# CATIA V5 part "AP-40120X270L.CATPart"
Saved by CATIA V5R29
Part number: AP-40120X270L
Bounding box of the stored display mesh (mm): x -135 to 135, y -60 to 60, z -20 to 20
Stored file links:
  C:\Users\Administrator\Desktop\프로젝트\Boxfold\AP-40120X270L.CATPart
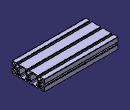
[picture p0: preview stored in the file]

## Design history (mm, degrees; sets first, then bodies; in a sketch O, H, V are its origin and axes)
Body1 (main body)
  Sketch1 on yz-plane, origin (0, 0, 0), H (0, 1, 0), V (0, 0, 1)
    point P1 (-60, -19)
    circle A1 centre (53.5, -13.5) radius 4
    circle A2 centre (53.5, 13.5) radius 4
    circle A3 centre (-53.5, -13.5) radius 4
    circle A4 centre (-53.5, 13.5) radius 4
    arc A5 centre (-38.0088, -3.1185) radius 0.3 from (-37.7966, -2.9064) to (-38.1702, -2.8656) ccw
    line L1 (-37.7966, -2.9064) -> (-37.1018, -3.6012)
    arc A6 centre (-36.8897, -3.3891) radius 0.3 from (-37.1018, -3.6012) to (-36.6868, -3.6101) ccw
    arc A7 centre (-40, 0) radius 4.9 from (-36.6868, -3.6101) to (-36.3857, -3.3086) ccw
    arc A8 centre (-36.607, -3.106) radius 0.3 from (-36.3857, -3.3086) to (-36.3949, -2.8939) ccw
    line L2 (-36.3949, -2.8939) -> (-37.0904, -2.1983)
    arc A9 centre (-36.8783, -1.9862) radius 0.3 from (-37.1314, -1.8252) to (-37.0904, -2.1983) ccw
    arc A10 centre (-40, 0) radius 3.4 from (-37.1314, -1.8252) to (-37.1323, 1.8265) ccw
    arc A11 centre (-36.8792, 1.9877) radius 0.3 from (-37.0914, 2.1998) to (-37.1323, 1.8265) ccw
    line L3 (-37.0914, 2.1998) -> (-36.396, 2.8952)
    arc A12 centre (-36.6081, 3.1073) radius 0.3 from (-36.396, 2.8952) to (-36.3869, 3.31) ccw
    arc A13 centre (-40, 0) radius 4.9 from (-36.3869, 3.31) to (-36.6881, 3.6113) ccw
    arc A14 centre (-36.8909, 3.3902) radius 0.3 from (-36.6881, 3.6113) to (-37.103, 3.6024) ccw
    line L4 (-37.103, 3.6024) -> (-37.7981, 2.9073)
    arc A15 centre (-38.0102, 3.1194) radius 0.3 from (-38.1716, 2.8665) to (-37.7981, 2.9073) ccw
    arc A16 centre (-40, 0) radius 3.4 from (-38.1716, 2.8665) to (-41.8252, 2.8686) ccw
    arc A17 centre (-41.9862, 3.1217) radius 0.3 from (-42.1983, 2.9096) to (-41.8252, 2.8686) ccw
    line L5 (-42.1983, 2.9096) -> (-42.8939, 3.6051)
    arc A18 centre (-43.106, 3.393) radius 0.3 from (-42.8939, 3.6051) to (-43.3086, 3.6143) ccw
    arc A19 centre (-40, 0) radius 4.9 from (-43.3086, 3.6143) to (-43.6101, 3.3132) ccw
    arc A20 centre (-43.3891, 3.1103) radius 0.3 from (-43.6101, 3.3132) to (-43.6012, 2.8982) ccw
    line L6 (-43.6012, 2.8982) -> (-42.9064, 2.2034)
    arc A21 centre (-43.1185, 1.9912) radius 0.3 from (-42.8656, 1.8298) to (-42.9064, 2.2034) ccw
    arc A22 centre (-40, 0) radius 3.4 from (-42.8656, 1.8298) to (-42.8665, -1.8284) ccw
    arc A23 centre (-43.1194, -1.9898) radius 0.3 from (-42.9073, -2.2019) to (-42.8665, -1.8284) ccw
    line L7 (-42.9073, -2.2019) -> (-43.6024, -2.897)
    arc A24 centre (-43.3902, -3.1091) radius 0.3 from (-43.6024, -2.897) to (-43.6113, -3.3119) ccw
    arc A25 centre (-40, 0) radius 4.9 from (-43.6113, -3.3119) to (-43.31, -3.6131) ccw
    arc A26 centre (-43.1073, -3.3919) radius 0.3 from (-43.31, -3.6131) to (-42.8952, -3.604) ccw
    line L8 (-42.8952, -3.604) -> (-42.1998, -2.9086)
    arc A27 centre (-41.9877, -3.1208) radius 0.3 from (-41.8265, -2.8677) to (-42.1998, -2.9086) ccw
    arc A28 centre (-40, 0) radius 3.4 from (-41.8265, -2.8677) to (-38.1702, -2.8656) ccw
    line L9 (39.6951, 6.0049) -> (40, 5.7)
    line L10 (40, 5.7) -> (40.3049, 6.0049)
    arc A29 centre (40, 15.5) radius 9.5 from (40.3049, 6.0049) to (47.0734, 9.1583) ccw
    arc A30 centre (46.85, 9.3585) radius 0.3 from (47.0734, 9.1583) to (47.15, 9.3585) ccw
    line L11 (47.15, 9.3585) -> (47.15, 15.7)
    arc A31 centre (46.85, 15.7) radius 0.3 from (47.15, 15.7) to (46.85, 16) ccw
    line L12 (46.85, 16) -> (44.65, 16)
    arc A32 centre (44.65, 16.5) radius 0.5 from (44.15, 16.5) to (44.65, 16) ccw
    line L13 (44.15, 16.5) -> (44.15, 19.5)
    arc A33 centre (44.65, 19.5) radius 0.5 from (44.65, 20) to (44.15, 19.5) ccw
    line L14 (44.65, 20) -> (59, 20)
    arc A34 centre (59, 19) radius 1 from (60, 19) to (59, 20) ccw
    line L15 (60, 19) -> (60, 4.65)
    arc A35 centre (59.5, 4.65) radius 0.5 from (59.5, 4.15) to (60, 4.65) ccw
    line L16 (59.5, 4.15) -> (56.5, 4.15)
    arc A36 centre (56.5, 4.65) radius 0.5 from (56, 4.65) to (56.5, 4.15) ccw
    line L17 (56, 4.65) -> (56, 6.85)
    arc A37 centre (55.7, 6.85) radius 0.3 from (56, 6.85) to (55.7, 7.15) ccw
    line L18 (55.7, 7.15) -> (49.3585, 7.15)
    arc A38 centre (49.3585, 6.85) radius 0.3 from (49.3585, 7.15) to (49.1583, 7.0734) ccw
    arc A39 centre (55.5, 0) radius 9.5 from (49.1583, 7.0734) to (46.0049, 0.3049) ccw
    line L19 (46.0049, 0.3049) -> (45.7, 0)
    line L20 (45.7, 0) -> (46.0049, -0.3049)
    arc A40 centre (55.5, 0) radius 9.5 from (46.0049, -0.3049) to (49.1583, -7.0734) ccw
    arc A41 centre (49.3585, -6.85) radius 0.3 from (49.1583, -7.0734) to (49.3585, -7.15) ccw
    line L21 (49.3585, -7.15) -> (55.7, -7.15)
    arc A42 centre (55.7, -6.85) radius 0.3 from (55.7, -7.15) to (56, -6.85) ccw
    line L22 (56, -6.85) -> (56, -4.65)
    arc A43 centre (56.5, -4.65) radius 0.5 from (56.5, -4.15) to (56, -4.65) ccw
    line L23 (56.5, -4.15) -> (59.5, -4.15)
    arc A44 centre (59.5, -4.65) radius 0.5 from (60, -4.65) to (59.5, -4.15) ccw
    line L24 (60, -4.65) -> (60, -19)
    arc A45 centre (59, -19) radius 1 from (59, -20) to (60, -19) ccw
    line L25 (59, -20) -> (44.65, -20)
    arc A46 centre (44.65, -19.5) radius 0.5 from (44.15, -19.5) to (44.65, -20) ccw
    line L26 (44.15, -19.5) -> (44.15, -16.5)
    arc A47 centre (44.65, -16.5) radius 0.5 from (44.65, -16) to (44.15, -16.5) ccw
    line L27 (44.65, -16) -> (46.85, -16)
    arc A48 centre (46.85, -15.7) radius 0.3 from (46.85, -16) to (47.15, -15.7) ccw
    line L28 (47.15, -15.7) -> (47.15, -9.3585)
    arc A49 centre (46.85, -9.3585) radius 0.3 from (47.15, -9.3585) to (47.0734, -9.1583) ccw
    arc A50 centre (40, -15.5) radius 9.5 from (47.0734, -9.1583) to (40.3049, -6.0049) ccw
    line L29 (40.3049, -6.0049) -> (40, -5.7)
    line L30 (40, -5.7) -> (39.6951, -6.0049)
    arc A51 centre (40, -15.5) radius 9.5 from (39.6951, -6.0049) to (32.9266, -9.1583) ccw
    arc A52 centre (33.15, -9.3585) radius 0.3 from (32.9266, -9.1583) to (32.85, -9.3585) ccw
    line L31 (32.85, -9.3585) -> (32.85, -15.7)
    arc A53 centre (33.15, -15.7) radius 0.3 from (32.85, -15.7) to (33.15, -16) ccw
    line L32 (33.15, -16) -> (35.35, -16)
    arc A54 centre (35.35, -16.5) radius 0.5 from (35.85, -16.5) to (35.35, -16) ccw
    line L33 (35.85, -16.5) -> (35.85, -19.5)
    arc A55 centre (35.35, -19.5) radius 0.5 from (35.35, -20) to (35.85, -19.5) ccw
    line L34 (35.35, -20) -> (4.65, -20)
    arc A56 centre (4.65, -19.5) radius 0.5 from (4.15, -19.5) to (4.65, -20) ccw
    line L35 (4.15, -19.5) -> (4.15, -16.5)
    arc A57 centre (4.65, -16.5) radius 0.5 from (4.65, -16) to (4.15, -16.5) ccw
    line L36 (4.65, -16) -> (6.85, -16)
    arc A58 centre (6.85, -15.7) radius 0.3 from (6.85, -16) to (7.15, -15.7) ccw
    line L37 (7.15, -15.7) -> (7.15, -9.3585)
    arc A59 centre (6.85, -9.3585) radius 0.3 from (7.15, -9.3585) to (7.0734, -9.1583) ccw
    arc A60 centre (0, -15.5) radius 9.5 from (7.0734, -9.1583) to (0.3049, -6.0049) ccw
    line L38 (0.3049, -6.0049) -> (0, -5.7)
    line L39 (0, -5.7) -> (-0.3049, -6.0049)
    arc A61 centre (0, -15.5) radius 9.5 from (-0.3049, -6.0049) to (-7.0734, -9.1583) ccw
    arc A62 centre (-6.85, -9.3585) radius 0.3 from (-7.0734, -9.1583) to (-7.15, -9.3585) ccw
    line L40 (-7.15, -9.3585) -> (-7.15, -15.7)
    arc A63 centre (-6.85, -15.7) radius 0.3 from (-7.15, -15.7) to (-6.85, -16) ccw
    line L41 (-6.85, -16) -> (-4.65, -16)
    arc A64 centre (-4.65, -16.5) radius 0.5 from (-4.15, -16.5) to (-4.65, -16) ccw
    line L42 (-4.15, -16.5) -> (-4.15, -19.5)
    arc A65 centre (-4.65, -19.5) radius 0.5 from (-4.65, -20) to (-4.15, -19.5) ccw
    line L43 (-4.65, -20) -> (-35.35, -20)
    arc A66 centre (-35.35, -19.5) radius 0.5 from (-35.85, -19.5) to (-35.35, -20) ccw
    line L44 (-35.85, -19.5) -> (-35.85, -16.5)
    arc A67 centre (-35.35, -16.5) radius 0.5 from (-35.35, -16) to (-35.85, -16.5) ccw
    line L45 (-35.35, -16) -> (-33.15, -16)
    arc A68 centre (-33.15, -15.7) radius 0.3 from (-33.15, -16) to (-32.85, -15.7) ccw
    line L46 (-32.85, -15.7) -> (-32.85, -9.3585)
    arc A69 centre (-33.15, -9.3585) radius 0.3 from (-32.85, -9.3585) to (-32.9266, -9.1583) ccw
    arc A70 centre (-40, -15.5) radius 9.5 from (-32.9266, -9.1583) to (-39.6951, -6.0049) ccw
    line L47 (-39.6951, -6.0049) -> (-40, -5.7)
    line L48 (-40, -5.7) -> (-40.3049, -6.0049)
    arc A71 centre (-40, -15.5) radius 9.5 from (-40.3049, -6.0049) to (-47.0734, -9.1583) ccw
    arc A72 centre (-46.85, -9.3585) radius 0.3 from (-47.0734, -9.1583) to (-47.15, -9.3585) ccw
    line L49 (-47.15, -9.3585) -> (-47.15, -15.7)
    arc A73 centre (-46.85, -15.7) radius 0.3 from (-47.15, -15.7) to (-46.85, -16) ccw
    line L50 (-46.85, -16) -> (-44.65, -16)
    arc A74 centre (-44.65, -16.5) radius 0.5 from (-44.15, -16.5) to (-44.65, -16) ccw
    line L51 (-44.15, -16.5) -> (-44.15, -19.5)
    arc A75 centre (-44.65, -19.5) radius 0.5 from (-44.65, -20) to (-44.15, -19.5) ccw
    line L52 (-44.65, -20) -> (-58, -20)
    line L53 (-58, -20) -> (-59, -20)
    arc A76 centre (-59, -19) radius 1 from (-60, -19) to (-59, -20) ccw
    line L54 (-60, -19) -> (-60, -4.65)
    arc A77 centre (-59.5, -4.65) radius 0.5 from (-59.5, -4.15) to (-60, -4.65) ccw
    line L55 (-59.5, -4.15) -> (-56.5, -4.15)
    arc A78 centre (-56.5, -4.65) radius 0.5 from (-56, -4.65) to (-56.5, -4.15) ccw
    line L56 (-56, -4.65) -> (-56, -6.85)
    arc A79 centre (-55.7, -6.85) radius 0.3 from (-56, -6.85) to (-55.7, -7.15) ccw
    line L57 (-55.7, -7.15) -> (-49.3585, -7.15)
    arc A80 centre (-49.3585, -6.85) radius 0.3 from (-49.3585, -7.15) to (-49.1583, -7.0734) ccw
    arc A81 centre (-55.5, 0) radius 9.5 from (-49.1583, -7.0734) to (-46.0049, -0.3049) ccw
    line L58 (-46.0049, -0.3049) -> (-45.7, 0)
    line L59 (-45.7, 0) -> (-46.0049, 0.3049)
    arc A82 centre (-55.5, 0) radius 9.5 from (-46.0049, 0.3049) to (-49.1583, 7.0734) ccw
    arc A83 centre (-49.3585, 6.85) radius 0.3 from (-49.1583, 7.0734) to (-49.3585, 7.15) ccw
    line L60 (-49.3585, 7.15) -> (-55.7, 7.15)
    arc A84 centre (-55.7, 6.85) radius 0.3 from (-55.7, 7.15) to (-56, 6.85) ccw
    line L61 (-56, 6.85) -> (-56, 4.65)
    arc A85 centre (-56.5, 4.65) radius 0.5 from (-56.5, 4.15) to (-56, 4.65) ccw
    line L62 (-56.5, 4.15) -> (-59.5, 4.15)
    arc A86 centre (-59.5, 4.65) radius 0.5 from (-60, 4.65) to (-59.5, 4.15) ccw
    line L63 (-60, 4.65) -> (-60, 19)
    arc A87 centre (-59, 19) radius 1 from (-59, 20) to (-60, 19) ccw
    line L64 (-59, 20) -> (-58, 20)
    line L65 (-58, 20) -> (-44.65, 20)
    arc A88 centre (-44.65, 19.5) radius 0.5 from (-44.15, 19.5) to (-44.65, 20) ccw
    line L66 (-44.15, 19.5) -> (-44.15, 16.5)
    arc A89 centre (-44.65, 16.5) radius 0.5 from (-44.65, 16) to (-44.15, 16.5) ccw
    line L67 (-44.65, 16) -> (-46.85, 16)
    arc A90 centre (-46.85, 15.7) radius 0.3 from (-46.85, 16) to (-47.15, 15.7) ccw
    line L68 (-47.15, 15.7) -> (-47.15, 9.3585)
    arc A91 centre (-46.85, 9.3585) radius 0.3 from (-47.15, 9.3585) to (-47.0734, 9.1583) ccw
    arc A92 centre (-40, 15.5) radius 9.5 from (-47.0734, 9.1583) to (-40.3049, 6.0049) ccw
    line L69 (-40.3049, 6.0049) -> (-40, 5.7)
    line L70 (-40, 5.7) -> (-39.6951, 6.0049)
    arc A93 centre (-40, 15.5) radius 9.5 from (-39.6951, 6.0049) to (-32.9266, 9.1583) ccw
    arc A94 centre (-33.15, 9.3585) radius 0.3 from (-32.9266, 9.1583) to (-32.85, 9.3585) ccw
    line L71 (-32.85, 9.3585) -> (-32.85, 15.7)
    arc A95 centre (-33.15, 15.7) radius 0.3 from (-32.85, 15.7) to (-33.15, 16) ccw
    line L72 (-33.15, 16) -> (-35.35, 16)
    arc A96 centre (-35.35, 16.5) radius 0.5 from (-35.85, 16.5) to (-35.35, 16) ccw
    line L73 (-35.85, 16.5) -> (-35.85, 19.5)
    arc A97 centre (-35.35, 19.5) radius 0.5 from (-35.35, 20) to (-35.85, 19.5) ccw
    line L74 (-35.35, 20) -> (-4.65, 20)
    arc A98 centre (-4.65, 19.5) radius 0.5 from (-4.15, 19.5) to (-4.65, 20) ccw
    line L75 (-4.15, 19.5) -> (-4.15, 16.5)
    arc A99 centre (-4.65, 16.5) radius 0.5 from (-4.65, 16) to (-4.15, 16.5) ccw
    line L76 (-4.65, 16) -> (-6.85, 16)
    arc A100 centre (-6.85, 15.7) radius 0.3 from (-6.85, 16) to (-7.15, 15.7) ccw
    line L77 (-7.15, 15.7) -> (-7.15, 9.3585)
    arc A101 centre (-6.85, 9.3585) radius 0.3 from (-7.15, 9.3585) to (-7.0734, 9.1583) ccw
    arc A102 centre (0, 15.5) radius 9.5 from (-7.0734, 9.1583) to (-0.3049, 6.0049) ccw
    line L78 (-0.3049, 6.0049) -> (0, 5.7)
    line L79 (0, 5.7) -> (0.3049, 6.0049)
    arc A103 centre (0, 15.5) radius 9.5 from (0.3049, 6.0049) to (7.0734, 9.1583) ccw
    arc A104 centre (6.85, 9.3585) radius 0.3 from (7.0734, 9.1583) to (7.15, 9.3585) ccw
    line L80 (7.15, 9.3585) -> (7.15, 15.7)
    arc A105 centre (6.85, 15.7) radius 0.3 from (7.15, 15.7) to (6.85, 16) ccw
    line L81 (6.85, 16) -> (4.65, 16)
    arc A106 centre (4.65, 16.5) radius 0.5 from (4.15, 16.5) to (4.65, 16) ccw
    line L82 (4.15, 16.5) -> (4.15, 19.5)
    arc A107 centre (4.65, 19.5) radius 0.5 from (4.65, 20) to (4.15, 19.5) ccw
    line L83 (4.65, 20) -> (35.35, 20)
    arc A108 centre (35.35, 19.5) radius 0.5 from (35.85, 19.5) to (35.35, 20) ccw
    line L84 (35.85, 19.5) -> (35.85, 16.5)
    arc A109 centre (35.35, 16.5) radius 0.5 from (35.35, 16) to (35.85, 16.5) ccw
    line L85 (35.35, 16) -> (33.15, 16)
    arc A110 centre (33.15, 15.7) radius 0.3 from (33.15, 16) to (32.85, 15.7) ccw
    line L86 (32.85, 15.7) -> (32.85, 9.3585)
    arc A111 centre (33.15, 9.3585) radius 0.3 from (32.85, 9.3585) to (32.9266, 9.1583) ccw
    arc A112 centre (40, 15.5) radius 9.5 from (32.9266, 9.1583) to (39.6951, 6.0049) ccw
    arc A113 centre (13.15, -14) radius 3 from (10.15, -14) to (13.15, -17) ccw
    line L87 (13.15, -17) -> (26.85, -17)
    arc A114 centre (26.85, -14) radius 3 from (26.85, -17) to (29.85, -14) ccw
    line L88 (29.85, -14) -> (29.85, -8.9422)
    arc A115 centre (20, -0.0053) radius 13.3 from (29.85, -8.9422) to (29.85, 8.9315) ccw
    line L89 (29.85, 8.9315) -> (29.85, 14)
    arc A116 centre (26.85, 14) radius 3 from (29.85, 14) to (26.85, 17) ccw
    line L90 (26.85, 17) -> (13.15, 17)
    arc A117 centre (13.15, 14) radius 3 from (13.15, 17) to (10.15, 14) ccw
    line L91 (10.15, 14) -> (10.15, 8.9315)
    arc A118 centre (20, -0.0053) radius 13.3 from (10.15, 8.9315) to (10.15, -8.9422) ccw
    line L92 (10.15, -8.9422) -> (10.15, -14)
    arc A119 centre (1.9912, -3.1185) radius 0.3 from (2.2034, -2.9064) to (1.8298, -2.8656) ccw
    line L93 (2.2034, -2.9064) -> (2.8982, -3.6012)
    arc A120 centre (3.1103, -3.3891) radius 0.3 from (2.8982, -3.6012) to (3.3132, -3.6101) ccw
    arc A121 centre (0, 0) radius 4.9 from (3.3132, -3.6101) to (3.6143, -3.3086) ccw
    arc A122 centre (3.393, -3.106) radius 0.3 from (3.6143, -3.3086) to (3.6051, -2.8939) ccw
    line L94 (3.6051, -2.8939) -> (2.9096, -2.1983)
    arc A123 centre (3.1217, -1.9862) radius 0.3 from (2.8686, -1.8252) to (2.9096, -2.1983) ccw
    arc A124 centre (0, 0) radius 3.4 from (2.8686, -1.8252) to (2.8677, 1.8265) ccw
    arc A125 centre (3.1208, 1.9877) radius 0.3 from (2.9086, 2.1998) to (2.8677, 1.8265) ccw
    line L95 (2.9086, 2.1998) -> (3.604, 2.8952)
    arc A126 centre (3.3919, 3.1073) radius 0.3 from (3.604, 2.8952) to (3.6131, 3.31) ccw
    arc A127 centre (0, 0) radius 4.9 from (3.6131, 3.31) to (3.3119, 3.6113) ccw
    arc A128 centre (3.1091, 3.3902) radius 0.3 from (3.3119, 3.6113) to (2.897, 3.6024) ccw
    line L96 (2.897, 3.6024) -> (2.2019, 2.9073)
    arc A129 centre (1.9898, 3.1194) radius 0.3 from (1.8284, 2.8665) to (2.2019, 2.9073) ccw
    arc A130 centre (0, 0) radius 3.4 from (1.8284, 2.8665) to (-1.8252, 2.8686) ccw
    arc A131 centre (-1.9862, 3.1217) radius 0.3 from (-2.1983, 2.9096) to (-1.8252, 2.8686) ccw
    line L97 (-2.1983, 2.9096) -> (-2.8939, 3.6051)
    arc A132 centre (-3.106, 3.393) radius 0.3 from (-2.8939, 3.6051) to (-3.3086, 3.6143) ccw
    arc A133 centre (0, 0) radius 4.9 from (-3.3086, 3.6143) to (-3.6101, 3.3132) ccw
    arc A134 centre (-3.3891, 3.1103) radius 0.3 from (-3.6101, 3.3132) to (-3.6012, 2.8982) ccw
    line L98 (-3.6012, 2.8982) -> (-2.9064, 2.2034)
    arc A135 centre (-3.1185, 1.9912) radius 0.3 from (-2.8656, 1.8298) to (-2.9064, 2.2034) ccw
    arc A136 centre (0, 0) radius 3.4 from (-2.8656, 1.8298) to (-2.8665, -1.8284) ccw
    arc A137 centre (-3.1194, -1.9898) radius 0.3 from (-2.9073, -2.2019) to (-2.8665, -1.8284) ccw
    line L99 (-2.9073, -2.2019) -> (-3.6024, -2.897)
    arc A138 centre (-3.3902, -3.1091) radius 0.3 from (-3.6024, -2.897) to (-3.6113, -3.3119) ccw
    arc A139 centre (0, 0) radius 4.9 from (-3.6113, -3.3119) to (-3.31, -3.6131) ccw
    arc A140 centre (-3.1073, -3.3919) radius 0.3 from (-3.31, -3.6131) to (-2.8952, -3.604) ccw
    line L100 (-2.8952, -3.604) -> (-2.1998, -2.9086)
    arc A141 centre (-1.9877, -3.1208) radius 0.3 from (-1.8265, -2.8677) to (-2.1998, -2.9086) ccw
    arc A142 centre (0, 0) radius 3.4 from (-1.8265, -2.8677) to (1.8298, -2.8656) ccw
    arc A143 centre (41.9912, -3.1185) radius 0.3 from (42.2034, -2.9064) to (41.8298, -2.8656) ccw
    line L101 (42.2034, -2.9064) -> (42.8982, -3.6012)
    arc A144 centre (43.1103, -3.3891) radius 0.3 from (42.8982, -3.6012) to (43.3132, -3.6101) ccw
    arc A145 centre (40, 0) radius 4.9 from (43.3132, -3.6101) to (43.6143, -3.3086) ccw
    arc A146 centre (43.393, -3.106) radius 0.3 from (43.6143, -3.3086) to (43.6051, -2.8939) ccw
    line L102 (43.6051, -2.8939) -> (42.9096, -2.1983)
    arc A147 centre (43.1217, -1.9862) radius 0.3 from (42.8686, -1.8252) to (42.9096, -2.1983) ccw
    arc A148 centre (40, 0) radius 3.4 from (42.8686, -1.8252) to (42.8677, 1.8265) ccw
    arc A149 centre (43.1208, 1.9877) radius 0.3 from (42.9086, 2.1998) to (42.8677, 1.8265) ccw
    line L103 (42.9086, 2.1998) -> (43.604, 2.8952)
    arc A150 centre (43.3919, 3.1073) radius 0.3 from (43.604, 2.8952) to (43.6131, 3.31) ccw
    arc A151 centre (40, 0) radius 4.9 from (43.6131, 3.31) to (43.3119, 3.6113) ccw
    arc A152 centre (43.1091, 3.3902) radius 0.3 from (43.3119, 3.6113) to (42.897, 3.6024) ccw
    line L104 (42.897, 3.6024) -> (42.2019, 2.9073)
    arc A153 centre (41.9898, 3.1194) radius 0.3 from (41.8284, 2.8665) to (42.2019, 2.9073) ccw
    arc A154 centre (40, 0) radius 3.4 from (41.8284, 2.8665) to (38.1748, 2.8686) ccw
    arc A155 centre (38.0138, 3.1217) radius 0.3 from (37.8017, 2.9096) to (38.1748, 2.8686) ccw
    line L105 (37.8017, 2.9096) -> (37.1061, 3.6051)
    arc A156 centre (36.894, 3.393) radius 0.3 from (37.1061, 3.6051) to (36.6914, 3.6143) ccw
    arc A157 centre (40, 0) radius 4.9 from (36.6914, 3.6143) to (36.3899, 3.3132) ccw
    arc A158 centre (36.6109, 3.1103) radius 0.3 from (36.3899, 3.3132) to (36.3988, 2.8982) ccw
    line L106 (36.3988, 2.8982) -> (37.0936, 2.2034)
    arc A159 centre (36.8815, 1.9912) radius 0.3 from (37.1344, 1.8298) to (37.0936, 2.2034) ccw
    arc A160 centre (40, 0) radius 3.4 from (37.1344, 1.8298) to (37.1335, -1.8284) ccw
    arc A161 centre (36.8806, -1.9898) radius 0.3 from (37.0927, -2.2019) to (37.1335, -1.8284) ccw
    line L107 (37.0927, -2.2019) -> (36.3976, -2.897)
    arc A162 centre (36.6098, -3.1091) radius 0.3 from (36.3976, -2.897) to (36.3887, -3.3119) ccw
    arc A163 centre (40, 0) radius 4.9 from (36.3887, -3.3119) to (36.69, -3.6131) ccw
    arc A164 centre (36.8927, -3.3919) radius 0.3 from (36.69, -3.6131) to (37.1048, -3.604) ccw
    line L108 (37.1048, -3.604) -> (37.8002, -2.9086)
    arc A165 centre (38.0123, -3.1208) radius 0.3 from (38.1735, -2.8677) to (37.8002, -2.9086) ccw
    arc A166 centre (40, 0) radius 3.4 from (38.1735, -2.8677) to (41.8298, -2.8656) ccw
    line L109 (-13.15, 17) -> (-26.85, 17)
    arc A167 centre (-26.85, 14) radius 3 from (-26.85, 17) to (-29.85, 14) ccw
    line L110 (-29.85, 14) -> (-29.85, 8.9315)
    arc A168 centre (-20, -0.0053) radius 13.3 from (-29.85, 8.9315) to (-29.85, -8.9422) ccw
    line L111 (-29.85, -8.9422) -> (-29.85, -14)
    arc A169 centre (-26.85, -14) radius 3 from (-29.85, -14) to (-26.85, -17) ccw
    line L112 (-26.85, -17) -> (-13.15, -17)
    arc A170 centre (-13.15, -14) radius 3 from (-13.15, -17) to (-10.15, -14) ccw
    line L113 (-10.15, -14) -> (-10.15, -8.9422)
    arc A171 centre (-20, -0.0053) radius 13.3 from (-10.15, -8.9422) to (-10.15, 8.9315) ccw
    line L114 (-10.15, 8.9315) -> (-10.15, 14)
    arc A172 centre (-13.15, 14) radius 3 from (-10.15, 14) to (-13.15, 17) ccw
    point P2 (-37.7966, -2.9064)
    point P3 (-38.1702, -2.8656)
    point P4 (-37.7966, -2.9064)
    point P5 (-37.1018, -3.6012)
    point P6 (-37.1018, -3.6012)
    point P7 (-36.6868, -3.6101)
    point P8 (-36.6868, -3.6101)
    point P9 (-36.3857, -3.3086)
    point P10 (-36.3857, -3.3086)
    point P11 (-36.3949, -2.8939)
    point P12 (-36.3949, -2.8939)
    point P13 (-37.0904, -2.1983)
    point P14 (-37.1314, -1.8252)
    point P15 (-37.0904, -2.1983)
    point P16 (-37.1314, -1.8252)
    point P17 (-37.1323, 1.8265)
    point P18 (-37.0914, 2.1998)
    point P19 (-37.1323, 1.8265)
    point P20 (-37.0914, 2.1998)
    point P21 (-36.396, 2.8952)
    point P22 (-36.396, 2.8952)
    point P23 (-36.3869, 3.31)
    point P24 (-36.3869, 3.31)
    point P25 (-36.6881, 3.6113)
    point P26 (-36.6881, 3.6113)
    point P27 (-37.103, 3.6024)
    point P28 (-37.103, 3.6024)
    point P29 (-37.7981, 2.9073)
    point P30 (-38.1716, 2.8665)
    point P31 (-37.7981, 2.9073)
    point P32 (-38.1716, 2.8665)
    point P33 (-41.8252, 2.8686)
    point P34 (-42.1983, 2.9096)
    point P35 (-41.8252, 2.8686)
    point P36 (-42.1983, 2.9096)
    point P37 (-42.8939, 3.6051)
    point P38 (-42.8939, 3.6051)
    point P39 (-43.3086, 3.6143)
    point P40 (-43.3086, 3.6143)
    point P41 (-43.6101, 3.3132)
    point P42 (-43.6101, 3.3132)
    point P43 (-43.6012, 2.8982)
    point P44 (-43.6012, 2.8982)
    point P45 (-42.9064, 2.2034)
    point P46 (-42.8656, 1.8298)
    point P47 (-42.9064, 2.2034)
    point P48 (-42.8656, 1.8298)
    point P49 (-42.8665, -1.8284)
    point P50 (-42.9073, -2.2019)
    point P51 (-42.8665, -1.8284)
    point P52 (-42.9073, -2.2019)
    point P53 (-43.6024, -2.897)
    point P54 (-43.6024, -2.897)
    point P55 (-43.6113, -3.3119)
    point P56 (-43.6113, -3.3119)
    point P57 (-43.31, -3.6131)
    point P58 (-43.31, -3.6131)
    point P59 (-42.8952, -3.604)
    point P60 (-42.8952, -3.604)
    point P61 (-42.1998, -2.9086)
    point P62 (-41.8265, -2.8677)
    point P63 (-42.1998, -2.9086)
    point P64 (-41.8265, -2.8677)
    point P65 (-38.1702, -2.8656)
    point P66 (39.6951, 6.0049)
    point P67 (40, 5.7)
    point P68 (40, 5.7)
    point P69 (40.3049, 6.0049)
    point P70 (40.3049, 6.0049)
    point P71 (47.0734, 9.1583)
    point P72 (47.0734, 9.1583)
    point P73 (47.15, 9.3585)
    point P74 (47.15, 9.3585)
    point P75 (47.15, 15.7)
    point P76 (47.15, 15.7)
    point P77 (46.85, 16)
    point P78 (46.85, 16)
    point P79 (44.65, 16)
    point P80 (44.15, 16.5)
    point P81 (44.65, 16)
    point P82 (44.15, 16.5)
    point P83 (44.15, 19.5)
    point P84 (44.65, 20)
    point P85 (44.15, 19.5)
    point P86 (44.65, 20)
    point P87 (59, 20)
    point P88 (60, 19)
    point P89 (59, 20)
    point P90 (60, 19)
    point P91 (60, 4.65)
    point P92 (59.5, 4.15)
    point P93 (60, 4.65)
    point P94 (59.5, 4.15)
    point P95 (56.5, 4.15)
    point P96 (56, 4.65)
    point P97 (56.5, 4.15)
    point P98 (56, 4.65)
    point P99 (56, 6.85)
    point P100 (56, 6.85)
    point P101 (55.7, 7.15)
    point P102 (55.7, 7.15)
    point P103 (49.3585, 7.15)
    point P104 (49.3585, 7.15)
    point P105 (49.1583, 7.0734)
    point P106 (49.1583, 7.0734)
    point P107 (46.0049, 0.3049)
    point P108 (46.0049, 0.3049)
    point P109 (45.7, 0)
    point P110 (45.7, 0)
    point P111 (46.0049, -0.3049)
    point P112 (46.0049, -0.3049)
    point P113 (49.1583, -7.0734)
    point P114 (49.1583, -7.0734)
    point P115 (49.3585, -7.15)
    point P116 (49.3585, -7.15)
    point P117 (55.7, -7.15)
    point P118 (55.7, -7.15)
    point P119 (56, -6.85)
    point P120 (56, -6.85)
    point P121 (56, -4.65)
    point P122 (56.5, -4.15)
    point P123 (56, -4.65)
    point P124 (56.5, -4.15)
    point P125 (59.5, -4.15)
    point P126 (60, -4.65)
    point P127 (59.5, -4.15)
    point P128 (60, -4.65)
    point P129 (60, -19)
    point P130 (59, -20)
    point P131 (60, -19)
    point P132 (59, -20)
    point P133 (44.65, -20)
    point P134 (44.15, -19.5)
    point P135 (44.65, -20)
    point P136 (44.15, -19.5)
    point P137 (44.15, -16.5)
    point P138 (44.65, -16)
    point P139 (44.15, -16.5)
    point P140 (44.65, -16)
    point P141 (46.85, -16)
    point P142 (46.85, -16)
    point P143 (47.15, -15.7)
    point P144 (47.15, -15.7)
    point P145 (47.15, -9.3585)
    point P146 (47.15, -9.3585)
    point P147 (47.0734, -9.1583)
    point P148 (47.0734, -9.1583)
    point P149 (40.3049, -6.0049)
    point P150 (40.3049, -6.0049)
    point P151 (40, -5.7)
    point P152 (40, -5.7)
    point P153 (39.6951, -6.0049)
    point P154 (39.6951, -6.0049)
    point P155 (32.9266, -9.1583)
    point P156 (32.9266, -9.1583)
    point P157 (32.85, -9.3585)
    point P158 (32.85, -9.3585)
    point P159 (32.85, -15.7)
    point P160 (32.85, -15.7)
    point P161 (33.15, -16)
    point P162 (33.15, -16)
    point P163 (35.35, -16)
    point P164 (35.85, -16.5)
    point P165 (35.35, -16)
    point P166 (35.85, -16.5)
    point P167 (35.85, -19.5)
    point P168 (35.35, -20)
    point P169 (35.85, -19.5)
    point P170 (35.35, -20)
    point P171 (4.65, -20)
    point P172 (4.15, -19.5)
    point P173 (4.65, -20)
    point P174 (4.15, -19.5)
    point P175 (4.15, -16.5)
    point P176 (4.65, -16)
    point P177 (4.15, -16.5)
    point P178 (4.65, -16)
    point P179 (6.85, -16)
    point P180 (6.85, -16)
    point P181 (7.15, -15.7)
    point P182 (7.15, -15.7)
    point P183 (7.15, -9.3585)
    point P184 (7.15, -9.3585)
    point P185 (7.0734, -9.1583)
    point P186 (7.0734, -9.1583)
    point P187 (0.3049, -6.0049)
    point P188 (0.3049, -6.0049)
    point P189 (0, -5.7)
    point P190 (0, -5.7)
    point P191 (-0.3049, -6.0049)
    point P192 (-0.3049, -6.0049)
    point P193 (-7.0734, -9.1583)
    point P194 (-7.0734, -9.1583)
    point P195 (-7.15, -9.3585)
    point P196 (-7.15, -9.3585)
    point P197 (-7.15, -15.7)
    point P198 (-7.15, -15.7)
    point P199 (-6.85, -16)
    point P200 (-6.85, -16)
    point P201 (-4.65, -16)
    point P202 (-4.15, -16.5)
    point P203 (-4.65, -16)
    point P204 (-4.15, -16.5)
    point P205 (-4.15, -19.5)
    point P206 (-4.65, -20)
    point P207 (-4.15, -19.5)
    point P208 (-4.65, -20)
    point P209 (-35.35, -20)
    point P210 (-35.85, -19.5)
    point P211 (-35.35, -20)
    point P212 (-35.85, -19.5)
    point P213 (-35.85, -16.5)
    point P214 (-35.35, -16)
    point P215 (-35.85, -16.5)
    point P216 (-35.35, -16)
    point P217 (-33.15, -16)
    point P218 (-33.15, -16)
    point P219 (-32.85, -15.7)
    point P220 (-32.85, -15.7)
    point P221 (-32.85, -9.3585)
    point P222 (-32.85, -9.3585)
    point P223 (-32.9266, -9.1583)
    point P224 (-32.9266, -9.1583)
    point P225 (-39.6951, -6.0049)
    point P226 (-39.6951, -6.0049)
    point P227 (-40, -5.7)
    point P228 (-40, -5.7)
    point P229 (-40.3049, -6.0049)
    point P230 (-40.3049, -6.0049)
    point P231 (-47.0734, -9.1583)
    point P232 (-47.0734, -9.1583)
    point P233 (-47.15, -9.3585)
    point P234 (-47.15, -9.3585)
    point P235 (-47.15, -15.7)
    point P236 (-47.15, -15.7)
    point P237 (-46.85, -16)
    point P238 (-46.85, -16)
    point P239 (-44.65, -16)
    point P240 (-44.15, -16.5)
    point P241 (-44.65, -16)
    point P242 (-44.15, -16.5)
    point P243 (-44.15, -19.5)
    point P244 (-44.65, -20)
    point P245 (-44.15, -19.5)
    point P246 (-44.65, -20)
    point P247 (-58, -20)
    point P248 (-58, -20)
    point P249 (-59, -20)
    point P250 (-60, -19)
    point P251 (-59, -20)
    point P252 (-60, -19)
    point P253 (-60, -4.65)
    point P254 (-59.5, -4.15)
    point P255 (-60, -4.65)
    point P256 (-59.5, -4.15)
    point P257 (-56.5, -4.15)
    point P258 (-56, -4.65)
    point P259 (-56.5, -4.15)
    point P260 (-56, -4.65)
    point P261 (-56, -6.85)
    point P262 (-56, -6.85)
    point P263 (-55.7, -7.15)
    point P264 (-55.7, -7.15)
    point P265 (-49.3585, -7.15)
    point P266 (-49.3585, -7.15)
    point P267 (-49.1583, -7.0734)
    point P268 (-49.1583, -7.0734)
    point P269 (-46.0049, -0.3049)
    point P270 (-46.0049, -0.3049)
    point P271 (-45.7, 0)
    point P272 (-45.7, 0)
    point P273 (-46.0049, 0.3049)
    point P274 (-46.0049, 0.3049)
    point P275 (-49.1583, 7.0734)
    point P276 (-49.1583, 7.0734)
    point P277 (-49.3585, 7.15)
    point P278 (-49.3585, 7.15)
    point P279 (-55.7, 7.15)
    point P280 (-55.7, 7.15)
    point P281 (-56, 6.85)
    point P282 (-56, 6.85)
    point P283 (-56, 4.65)
    point P284 (-56.5, 4.15)
    point P285 (-56, 4.65)
    point P286 (-56.5, 4.15)
    point P287 (-59.5, 4.15)
    point P288 (-60, 4.65)
    point P289 (-59.5, 4.15)
    point P290 (-60, 4.65)
    point P291 (-60, 19)
    point P292 (-59, 20)
    point P293 (-60, 19)
    point P294 (-59, 20)
    point P295 (-58, 20)
    point P296 (-58, 20)
    point P297 (-44.65, 20)
    point P298 (-44.15, 19.5)
    point P299 (-44.65, 20)
    point P300 (-44.15, 19.5)
    point P301 (-44.15, 16.5)
    point P302 (-44.65, 16)
    point P303 (-44.15, 16.5)
    point P304 (-44.65, 16)
    point P305 (-46.85, 16)
    point P306 (-46.85, 16)
    point P307 (-47.15, 15.7)
    point P308 (-47.15, 15.7)
    point P309 (-47.15, 9.3585)
    point P310 (-47.15, 9.3585)
    point P311 (-47.0734, 9.1583)
    point P312 (-47.0734, 9.1583)
    point P313 (-40.3049, 6.0049)
    point P314 (-40.3049, 6.0049)
    point P315 (-40, 5.7)
    point P316 (-40, 5.7)
    point P317 (-39.6951, 6.0049)
    point P318 (-39.6951, 6.0049)
    point P319 (-32.9266, 9.1583)
    point P320 (-32.9266, 9.1583)
    point P321 (-32.85, 9.3585)
    point P322 (-32.85, 9.3585)
    point P323 (-32.85, 15.7)
    point P324 (-32.85, 15.7)
    point P325 (-33.15, 16)
    point P326 (-33.15, 16)
    point P327 (-35.35, 16)
    point P328 (-35.85, 16.5)
    point P329 (-35.35, 16)
    point P330 (-35.85, 16.5)
    point P331 (-35.85, 19.5)
    point P332 (-35.35, 20)
    point P333 (-35.85, 19.5)
    point P334 (-35.35, 20)
    point P335 (-4.65, 20)
    point P336 (-4.15, 19.5)
    point P337 (-4.65, 20)
    point P338 (-4.15, 19.5)
    point P339 (-4.15, 16.5)
    point P340 (-4.65, 16)
    point P341 (-4.15, 16.5)
    point P342 (-4.65, 16)
    point P343 (-6.85, 16)
    point P344 (-6.85, 16)
    point P345 (-7.15, 15.7)
    point P346 (-7.15, 15.7)
    point P347 (-7.15, 9.3585)
    point P348 (-7.15, 9.3585)
    point P349 (-7.0734, 9.1583)
    point P350 (-7.0734, 9.1583)
    point P351 (-0.3049, 6.0049)
    point P352 (-0.3049, 6.0049)
    point P353 (0, 5.7)
    point P354 (0, 5.7)
    point P355 (0.3049, 6.0049)
    point P356 (0.3049, 6.0049)
    point P357 (7.0734, 9.1583)
    point P358 (7.0734, 9.1583)
    point P359 (7.15, 9.3585)
    point P360 (7.15, 9.3585)
    point P361 (7.15, 15.7)
    point P362 (7.15, 15.7)
    point P363 (6.85, 16)
    point P364 (6.85, 16)
    point P365 (4.65, 16)
    point P366 (4.15, 16.5)
    point P367 (4.65, 16)
    point P368 (4.15, 16.5)
    point P369 (4.15, 19.5)
    point P370 (4.65, 20)
    point P371 (4.15, 19.5)
    point P372 (4.65, 20)
    point P373 (35.35, 20)
    point P374 (35.85, 19.5)
    point P375 (35.35, 20)
    point P376 (35.85, 19.5)
    point P377 (35.85, 16.5)
    point P378 (35.35, 16)
    point P379 (35.85, 16.5)
    point P380 (35.35, 16)
    point P381 (33.15, 16)
    point P382 (33.15, 16)
    point P383 (32.85, 15.7)
    point P384 (32.85, 15.7)
    point P385 (32.85, 9.3585)
    point P386 (32.85, 9.3585)
    point P387 (32.9266, 9.1583)
    point P388 (32.9266, 9.1583)
    point P389 (39.6951, 6.0049)
    point P390 (10.15, -14)
    point P391 (13.15, -17)
    point P392 (13.15, -17)
    point P393 (26.85, -17)
    point P394 (26.85, -17)
    point P395 (29.85, -14)
    point P396 (29.85, -14)
    point P397 (29.85, -8.9422)
    point P398 (29.85, -8.9422)
    point P399 (29.85, 8.9315)
    point P400 (29.85, 8.9315)
    point P401 (29.85, 14)
    point P402 (29.85, 14)
    point P403 (26.85, 17)
    point P404 (26.85, 17)
    point P405 (13.15, 17)
    point P406 (13.15, 17)
    point P407 (10.15, 14)
    point P408 (10.15, 14)
    point P409 (10.15, 8.9315)
    point P410 (10.15, 8.9315)
    point P411 (10.15, -8.9422)
    point P412 (10.15, -8.9422)
    point P413 (10.15, -14)
    point P414 (2.2034, -2.9064)
    point P415 (1.8298, -2.8656)
    point P416 (2.2034, -2.9064)
    point P417 (2.8982, -3.6012)
    point P418 (2.8982, -3.6012)
    point P419 (3.3132, -3.6101)
    point P420 (3.3132, -3.6101)
    point P421 (3.6143, -3.3086)
    point P422 (3.6143, -3.3086)
    point P423 (3.6051, -2.8939)
    point P424 (3.6051, -2.8939)
    point P425 (2.9096, -2.1983)
    point P426 (2.8686, -1.8252)
    point P427 (2.9096, -2.1983)
    point P428 (2.8686, -1.8252)
    point P429 (2.8677, 1.8265)
    point P430 (2.9086, 2.1998)
    point P431 (2.8677, 1.8265)
    point P432 (2.9086, 2.1998)
    point P433 (3.604, 2.8952)
    point P434 (3.604, 2.8952)
    point P435 (3.6131, 3.31)
    point P436 (3.6131, 3.31)
    point P437 (3.3119, 3.6113)
    point P438 (3.3119, 3.6113)
    point P439 (2.897, 3.6024)
    point P440 (2.897, 3.6024)
    point P441 (2.2019, 2.9073)
    point P442 (1.8284, 2.8665)
    point P443 (2.2019, 2.9073)
    point P444 (1.8284, 2.8665)
    point P445 (-1.8252, 2.8686)
    point P446 (-2.1983, 2.9096)
    point P447 (-1.8252, 2.8686)
    point P448 (-2.1983, 2.9096)
    point P449 (-2.8939, 3.6051)
    point P450 (-2.8939, 3.6051)
    point P451 (-3.3086, 3.6143)
    point P452 (-3.3086, 3.6143)
    point P453 (-3.6101, 3.3132)
    point P454 (-3.6101, 3.3132)
    point P455 (-3.6012, 2.8982)
    point P456 (-3.6012, 2.8982)
    point P457 (-2.9064, 2.2034)
    point P458 (-2.8656, 1.8298)
    point P459 (-2.9064, 2.2034)
    point P460 (-2.8656, 1.8298)
    point P461 (-2.8665, -1.8284)
    point P462 (-2.9073, -2.2019)
    point P463 (-2.8665, -1.8284)
    point P464 (-2.9073, -2.2019)
    point P465 (-3.6024, -2.897)
    point P466 (-3.6024, -2.897)
    point P467 (-3.6113, -3.3119)
    point P468 (-3.6113, -3.3119)
    point P469 (-3.31, -3.6131)
    point P470 (-3.31, -3.6131)
    point P471 (-2.8952, -3.604)
    point P472 (-2.8952, -3.604)
    point P473 (-2.1998, -2.9086)
    point P474 (-1.8265, -2.8677)
    point P475 (-2.1998, -2.9086)
    point P476 (-1.8265, -2.8677)
    point P477 (1.8298, -2.8656)
    point P478 (42.2034, -2.9064)
    point P479 (41.8298, -2.8656)
    point P480 (42.2034, -2.9064)
    point P481 (42.8982, -3.6012)
    point P482 (42.8982, -3.6012)
    point P483 (43.3132, -3.6101)
    point P484 (43.3132, -3.6101)
    point P485 (43.6143, -3.3086)
    point P486 (43.6143, -3.3086)
    point P487 (43.6051, -2.8939)
    point P488 (43.6051, -2.8939)
    point P489 (42.9096, -2.1983)
    point P490 (42.8686, -1.8252)
    point P491 (42.9096, -2.1983)
    point P492 (42.8686, -1.8252)
    point P493 (42.8677, 1.8265)
    point P494 (42.9086, 2.1998)
    point P495 (42.8677, 1.8265)
    point P496 (42.9086, 2.1998)
    point P497 (43.604, 2.8952)
    point P498 (43.604, 2.8952)
    point P499 (43.6131, 3.31)
    point P500 (43.6131, 3.31)
    point P501 (43.3119, 3.6113)
    point P502 (43.3119, 3.6113)
    point P503 (42.897, 3.6024)
    point P504 (42.897, 3.6024)
    point P505 (42.2019, 2.9073)
    point P506 (41.8284, 2.8665)
    point P507 (42.2019, 2.9073)
    point P508 (41.8284, 2.8665)
    point P509 (38.1748, 2.8686)
    point P510 (37.8017, 2.9096)
    point P511 (38.1748, 2.8686)
    point P512 (37.8017, 2.9096)
    point P513 (37.1061, 3.6051)
    point P514 (37.1061, 3.6051)
    point P515 (36.6914, 3.6143)
    point P516 (36.6914, 3.6143)
    point P517 (36.3899, 3.3132)
    point P518 (36.3899, 3.3132)
    point P519 (36.3988, 2.8982)
    point P520 (36.3988, 2.8982)
    point P521 (37.0936, 2.2034)
    point P522 (37.1344, 1.8298)
    point P523 (37.0936, 2.2034)
    point P524 (37.1344, 1.8298)
    point P525 (37.1335, -1.8284)
    point P526 (37.0927, -2.2019)
    point P527 (37.1335, -1.8284)
    point P528 (37.0927, -2.2019)
    point P529 (36.3976, -2.897)
    point P530 (36.3976, -2.897)
    point P531 (36.3887, -3.3119)
    point P532 (36.3887, -3.3119)
    point P533 (36.69, -3.6131)
    point P534 (36.69, -3.6131)
    point P535 (37.1048, -3.604)
    point P536 (37.1048, -3.604)
    point P537 (37.8002, -2.9086)
    point P538 (38.1735, -2.8677)
    point P539 (37.8002, -2.9086)
    point P540 (38.1735, -2.8677)
    point P541 (41.8298, -2.8656)
    point P542 (-13.15, 17)
    point P543 (-26.85, 17)
    point P544 (-26.85, 17)
    point P545 (-29.85, 14)
    point P546 (-29.85, 14)
    point P547 (-29.85, 8.9315)
    point P548 (-29.85, 8.9315)
    point P549 (-29.85, -8.9422)
    point P550 (-29.85, -8.9422)
    point P551 (-29.85, -14)
    point P552 (-29.85, -14)
    point P553 (-26.85, -17)
    point P554 (-26.85, -17)
    point P555 (-13.15, -17)
    point P556 (-13.15, -17)
    point P557 (-10.15, -14)
    point P558 (-10.15, -14)
    point P559 (-10.15, -8.9422)
    point P560 (-10.15, -8.9422)
    point P561 (-10.15, 8.9315)
    point P562 (-10.15, 8.9315)
    point P563 (-10.15, 14)
    point P564 (-10.15, 14)
    point P565 (-13.15, 17)
    reference intersected line E1 through (0, 0) direction (0, 1) from zx-plane
    distance H L83 = 20
    distance L15 E1 = 60
    coincidence: P2 P4, P3 P65, P5 P6, P7 P8, P9 P10, P11 P12, P13 P15, P14 P16, P17 P19, P18 P20, P21 P22, P23 P24, P25 P26, P27 P28, P29 P31, P30 P32, P33 P35, P34 P36, P37 P38, P39 P40, P41 P42, P43 P44, P45 P47, P46 P48, P49 P51, P50 P52, P53 P54, P55 P56, P57 P58, P59 P60, P61 P63, P62 P64, P66 P389, P67 P68, P69 P70, P71 P72, P73 P74, P75 P76, P77 P78, P79 P81, P80 P82, P83 P85, P84 P86, P88 P90, P89 P87, P91 P93, P92 P94, P95 P97, P96 P98, P99 P100, P101 P102, P103 P104, P105 P106, P107 P108, P109 P110, P111 P112, P113 P114, P115 P116, P117 P118, P119 P120, P121 P123, P122 P124, P125 P127, P126 P128, P132 P130, P133 P135, P134 P136, P137 P139, P138 P140, P141 P142, P143 P144, P145 P146, P147 P148, P149 P150, P151 P152, P153 P154, P155 P156, P157 P158, P159 P160, P161 P162, P163 P165, P164 P166, P167 P169, P168 P170, P171 P173, P172 P174, P175 P177, P176 P178, P179 P180, P181 P182, P183 P184, P185 P186, P187 P188, P189 P190, P191 P192, P193 P194, P195 P196, P197 P198, P199 P200, P201 P203, P202 P204, P205 P207, P206 P208, P209 P211, P210 P212, P213 P215, P214 P216, P217 P218, P219 P220, P221 P222, P223 P224, P225 P226, P227 P228, P229 P230, P231 P232, P233 P234, P235 P236, P237 P238, P239 P241, P240 P242, P243 P245, P244 P246, P247 P248, P249 P251, P250 P252, P253 P255, P254 P256, P257 P259, P258 P260, P261 P262, P263 P264, P265 P266, P267 P268, P269 P270, P271 P272, P273 P274, P275 P276, P277 P278, P279 P280, P281 P282, P283 P285, P284 P286, P287 P289, P288 P290, P291 P293, P292 P294, P295 P296, P297 P299, P298 P300, P301 P303, P302 P304, P305 P306, P307 P308, P309 P310, P311 P312, P313 P314, P315 P316, P317 P318, P319 P320, P321 P322, P323 P324, P325 P326, P327 P329, P328 P330, P331 P333, P332 P334, P335 P337, P336 P338, P339 P341, P340 P342, P343 P344, P345 P346, P347 P348, P349 P350, P351 P352, P353 P354, P355 P356, P357 P358, P359 P360, P361 P362, P363 P364, P365 P367, P366 P368, P369 P371, P370 P372, P373 P375, P374 P376, P377 P379, P378 P380, P381 P382, P383 P384, P385 P386, P387 P388, P390 P413, P391 P392, P393 P394, P395 P396, P397 P398, P399 P400, P401 P402, P403 P404, P405 P406, P407 P408, P409 P410, P411 P412, P414 P416, P415 P477, P417 P418, P419 P420, P421 P422, P423 P424, P425 P427, P426 P428, P429 P431, P430 P432, P433 P434, P435 P436, P437 P438, P439 P440, P441 P443, P442 P444, P445 P447, P446 P448, P449 P450, P451 P452, P453 P454, P455 P456, P457 P459, P458 P460, P461 P463, P462 P464, P465 P466, P467 P468, P469 P470, P471 P472, P473 P475, P474 P476, P478 P480, P479 P541, P481 P482, P483 P484, P485 P486, P487 P488, P489 P491, P490 P492, P493 P495, P494 P496, P497 P498, P499 P500, P501 P502, P503 P504, P505 P507, P506 P508, P509 P511, P510 P512, P513 P514, P515 P516, P517 P518, P519 P520, P521 P523, P522 P524, P525 P527, P526 P528, P529 P530, P531 P532, P533 P534, P535 P536, P537 P539, P538 P540, P542 P565, P543 P544, P545 P546, P547 P548, P549 P550, P551 P552, P553 P554, P555 P556, P557 P558, P559 P560, P561 P562, P563 P564, P131 P129
  Pad1: profile Sketch1, direction (1, 0, 0), length 135, mirrored extent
